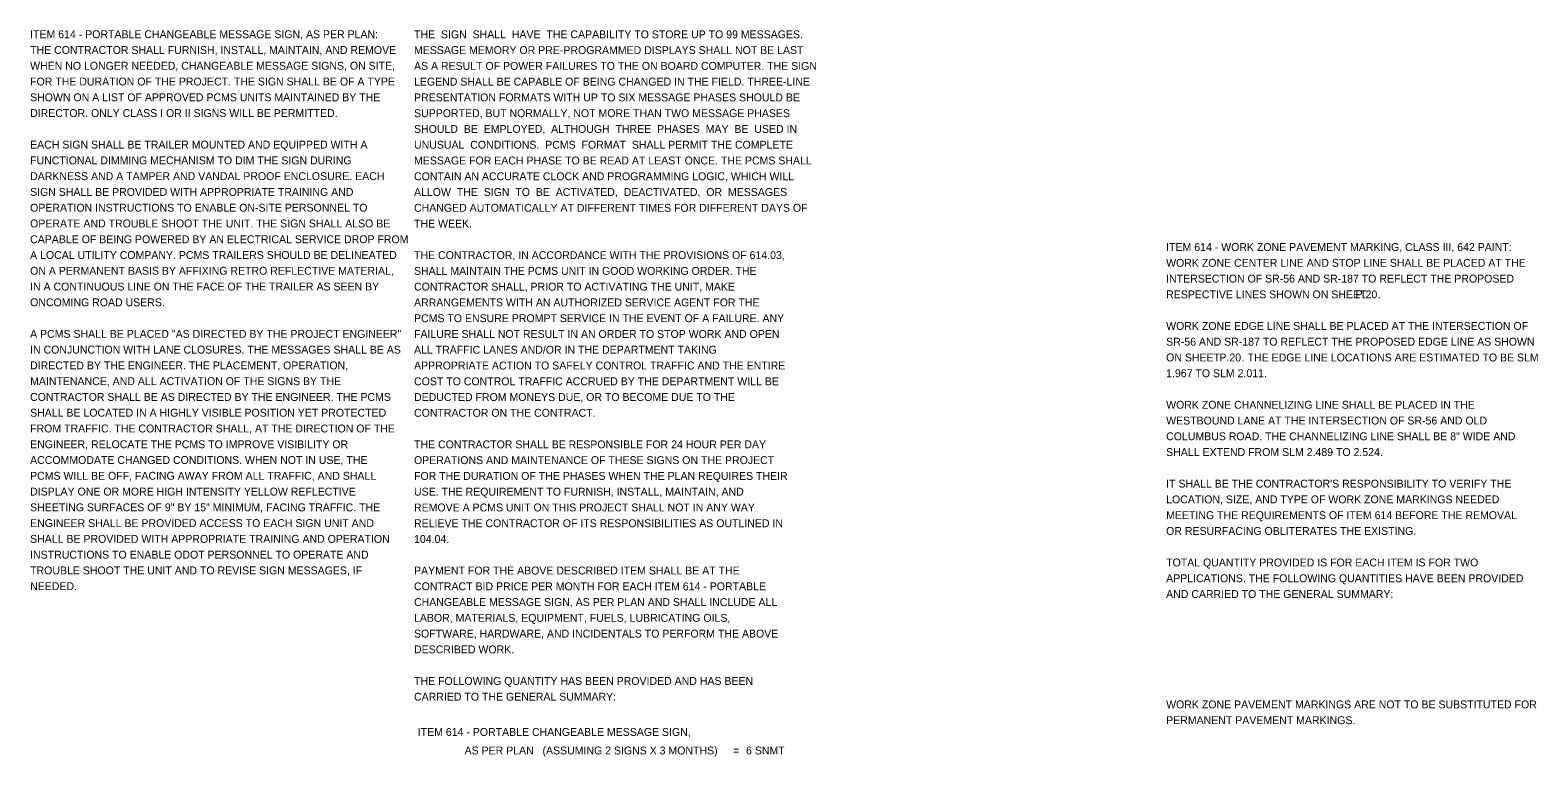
# Model space of a CAD drawing. Extents: x -7.9 to 64.5, y -13.1 to 23.6.
# Drawn here: x 37.77 to 64.55, y 7.89 to 20.79 of the extents above; entities that cross this region are included whole.
import ezdxf

# ---------------------------------------------------------------- set-up
doc = ezdxf.new("R2010")
doc.units = 0
doc.layers.add('SH_Text', color=7, linetype='Continuous')

msp = doc.modelspace()

# ---------------------------------------------------------------- texts
at = {"layer": 'SH_Text'}
for s, p in [('ITEM 614 - PORTABLE CHANGEABLE MESSAGE SIGN, AS PER PLAN:', (37.769, 20.651)), ('THE  SIGN  SHALL  HAVE  THE CAPABILITY TO STORE UP TO 99 MESSAGES.', (44.588, 20.649)), ('THE CONTRACTOR SHALL FURNISH, INSTALL, MAINTAIN, AND REMOVE ', (37.769, 20.371)), ('MESSAGE MEMORY OR PRE-PROGRAMMED DISPLAYS SHALL NOT BE LAST', (44.588, 20.369)), ('WHEN NO LONGER NEEDED, CHANGEABLE MESSAGE SIGNS, ON SITE, ', (37.769, 20.091)), ('AS A RESULT OF POWER FAILURES TO THE ON BOARD COMPUTER. THE SIGN', (44.588, 20.089)), ('FOR THE DURATION OF THE PROJECT. THE SIGN SHALL BE OF A TYPE ', (37.769, 19.811)), ('LEGEND SHALL BE CAPABLE OF BEING CHANGED IN THE FIELD. THREE-LINE', (44.588, 19.809)), ('SHOWN ON A LIST OF APPROVED PCMS UNITS MAINTAINED BY THE ', (37.769, 19.531)), ('PRESENTATION FORMATS WITH UP TO SIX MESSAGE PHASES SHOULD BE', (44.588, 19.529)), ('DIRECTOR. ONLY CLASS I OR II SIGNS WILL BE PERMITTED.', (37.769, 19.251)), ('SUPPORTED, BUT NORMALLY, NOT MORE THAN TWO MESSAGE PHASES', (44.588, 19.249)), ('SHOULD  BE  EMPLOYED,  ALTHOUGH  THREE  PHASES  MAY  BE  USED IN', (44.588, 18.969)), ('EACH SIGN SHALL BE TRAILER MOUNTED AND EQUIPPED WITH A ', (37.769, 18.691)), ('UNUSUAL  CONDITIONS.  PCMS  FORMAT  SHALL PERMIT THE COMPLETE', (44.588, 18.689)), ('FUNCTIONAL DIMMING MECHANISM TO DIM THE SIGN DURING ', (37.769, 18.411)), ('MESSAGE FOR EACH PHASE TO BE READ AT LEAST ONCE. THE PCMS SHALL', (44.588, 18.409)), ('DARKNESS AND A TAMPER AND VANDAL PROOF ENCLOSURE. EACH ', (37.769, 18.131)), ('CONTAIN AN ACCURATE CLOCK AND PROGRAMMING LOGIC, WHICH WILL', (44.588, 18.129)), ('SIGN SHALL BE PROVIDED WITH APPROPRIATE TRAINING AND ', (37.769, 17.851)), ('ALLOW  THE  SIGN  TO  BE  ACTIVATED,  DEACTIVATED,  OR  MESSAGES', (44.588, 17.849)), ('OPERATION INSTRUCTIONS TO ENABLE ON-SITE PERSONNEL TO ', (37.769, 17.571)), ('CHANGED AUTOMATICALLY AT DIFFERENT TIMES FOR DIFFERENT DAYS OF', (44.588, 17.569)), ('OPERATE AND TROUBLE SHOOT THE UNIT. THE SIGN SHALL ALSO BE ', (37.769, 17.291)), ('THE WEEK.', (44.588, 17.289)), ('CAPABLE OF BEING POWERED BY AN ELECTRICAL SERVICE DROP FROM ', (37.769, 17.011)), ('A LOCAL UTILITY COMPANY. PCMS TRAILERS SHOULD BE DELINEATED ', (37.769, 16.731)), ('ITEM 614 - WORK ZONE PAVEMENT MARKING, CLASS III, 642 PAINT:', (57.947, 16.872)), ('THE CONTRACTOR, IN ACCORDANCE WITH THE PROVISIONS OF 614.03, ', (44.588, 16.729)), ('WORK ZONE CENTER LINE AND STOP LINE SHALL BE PLACED AT THE ', (57.947, 16.592)), ('ON A PERMANENT BASIS BY AFFIXING RETRO REFLECTIVE MATERIAL, ', (37.769, 16.451)), ('SHALL MAINTAIN THE PCMS UNIT IN GOOD WORKING ORDER. THE ', (44.588, 16.449)), ('INTERSECTION OF SR-56 AND SR-187 TO REFLECT THE PROPOSED ', (57.947, 16.312)), ('IN A CONTINUOUS LINE ON THE FACE OF THE TRAILER AS SEEN BY ', (37.769, 16.171)), ('CONTRACTOR SHALL, PRIOR TO ACTIVATING THE UNIT, MAKE ', (44.588, 16.169)), ('RESPECTIVE LINES SHOWN ON SHEET ', (57.947, 16.032)), ('P.20', (61.312, 16.032)), ('ONCOMING ROAD USERS.', (37.769, 15.891)), ('ARRANGEMENTS WITH AN AUTHORIZED SERVICE AGENT FOR THE ', (44.588, 15.889)), ('.', (61.705, 16.032)), ('PCMS TO ENSURE PROMPT SERVICE IN THE EVENT OF A FAILURE. ANY ', (44.588, 15.609)), ('WORK ZONE EDGE LINE SHALL BE PLACED AT THE INTERSECTION OF ', (57.947, 15.472)), ('A PCMS SHALL BE PLACED "AS DIRECTED BY THE PROJECT ENGINEER" ', (37.769, 15.331)), ('FAILURE SHALL NOT RESULT IN AN ORDER TO STOP WORK AND OPEN ', (44.588, 15.329)), ('SR-56 AND SR-187 TO REFLECT THE PROPOSED EDGE LINE AS SHOWN ', (57.947, 15.192)), ('IN CONJUNCTION WITH LANE CLOSURES. THE MESSAGES SHALL BE AS ', (37.769, 15.051)), ('ALL TRAFFIC LANES AND/OR IN THE DEPARTMENT TAKING ', (44.588, 15.049)), ('ON SHEET ', (57.947, 14.912)), ('P.20', (58.893, 14.912)), (' THE EDGE LINE LOCATIONS ARE ESTIMATED TO BE SLM ', (59.342, 14.912)), ('DIRECTED BY THE ENGINEER. THE PLACEMENT, OPERATION, ', (37.769, 14.771)), ('APPROPRIATE ACTION TO SAFELY CONTROL TRAFFIC AND THE ENTIRE ', (44.588, 14.769)), ('1.967 TO SLM 2.011.', (57.947, 14.632)), ('.', (59.287, 14.912)), ('MAINTENANCE, AND ALL ACTIVATION OF THE SIGNS BY THE ', (37.769, 14.491)), ('COST TO CONTROL TRAFFIC ACCRUED BY THE DEPARTMENT WILL BE ', (44.588, 14.489)), ('CONTRACTOR SHALL BE AS DIRECTED BY THE ENGINEER. THE PCMS ', (37.769, 14.211)), ('DEDUCTED FROM MONEYS DUE, OR TO BECOME DUE TO THE ', (44.588, 14.209)), ('WORK ZONE CHANNELIZING LINE SHALL BE PLACED IN THE ', (57.947, 14.072)), ('SHALL BE LOCATED IN A HIGHLY VISIBLE POSITION YET PROTECTED ', (37.769, 13.931)), ('CONTRACTOR ON THE CONTRACT.', (44.588, 13.929)), ('WESTBOUND LANE AT THE INTERSECTION OF SR-56 AND OLD ', (57.947, 13.792)), ('FROM TRAFFIC. THE CONTRACTOR SHALL, AT THE DIRECTION OF THE ', (37.769, 13.651)), ('ENGINEER, RELOCATE THE PCMS TO IMPROVE VISIBILITY OR ', (37.769, 13.371)), ('THE CONTRACTOR SHALL BE RESPONSIBLE FOR 24 HOUR PER DAY ', (44.588, 13.369)), ('COLUMBUS ROAD. THE CHANNELIZING LINE SHALL BE 8" WIDE AND ', (57.947, 13.512)), ('ACCOMMODATE CHANGED CONDITIONS. WHEN NOT IN USE, THE ', (37.769, 13.091)), ('OPERATIONS AND MAINTENANCE OF THESE SIGNS ON THE PROJECT ', (44.588, 13.089)), ('SHALL EXTEND FROM SLM 2.489 TO 2.524.', (57.947, 13.232)), ('PCMS WILL BE OFF, FACING AWAY FROM ALL TRAFFIC, AND SHALL ', (37.769, 12.811)), ('FOR THE DURATION OF THE PHASES WHEN THE PLAN REQUIRES THEIR ', (44.588, 12.809)), ('DISPLAY ONE OR MORE HIGH INTENSITY YELLOW REFLECTIVE ', (37.769, 12.531)), ('USE. THE REQUIREMENT TO FURNISH, INSTALL, MAINTAIN, AND ', (44.588, 12.529)), ("IT SHALL BE THE CONTRACTOR'S RESPONSIBILITY TO VERIFY THE ", (57.947, 12.672)), ('SHEETING SURFACES OF 9" BY 15" MINIMUM, FACING TRAFFIC. THE ', (37.769, 12.251)), ('REMOVE A PCMS UNIT ON THIS PROJECT SHALL NOT IN ANY WAY ', (44.588, 12.249)), ('LOCATION, SIZE, AND TYPE OF WORK ZONE MARKINGS NEEDED ', (57.947, 12.392)), ('ENGINEER SHALL BE PROVIDED ACCESS TO EACH SIGN UNIT AND ', (37.769, 11.971)), ('RELIEVE THE CONTRACTOR OF ITS RESPONSIBILITIES AS OUTLINED IN ', (44.588, 11.969)), ('MEETING THE REQUIREMENTS OF ITEM 614 BEFORE THE REMOVAL ', (57.947, 12.112)), ('SHALL BE PROVIDED WITH APPROPRIATE TRAINING AND OPERATION ', (37.769, 11.691)), ('104.04.', (44.588, 11.689)), ('OR RESURFACING OBLITERATES THE EXISTING.', (57.947, 11.832)), ('INSTRUCTIONS TO ENABLE ODOT PERSONNEL TO OPERATE AND ', (37.769, 11.411)), ('TROUBLE SHOOT THE UNIT AND TO REVISE SIGN MESSAGES, IF ', (37.769, 11.131)), ('PAYMENT FOR THE ABOVE DESCRIBED ITEM SHALL BE AT THE ', (44.588, 11.129)), ('TOTAL QUANTITY PROVIDED IS FOR EACH ITEM IS FOR TWO ', (57.947, 11.272)), ('NEEDED.', (37.769, 10.851)), ('CONTRACT BID PRICE PER MONTH FOR EACH ITEM 614 - PORTABLE ', (44.588, 10.849)), ('APPLICATIONS. THE FOLLOWING QUANTITIES HAVE BEEN PROVIDED ', (57.947, 10.992)), ('AND CARRIED TO THE GENERAL SUMMARY:', (57.947, 10.712)), ('CHANGEABLE MESSAGE SIGN, AS PER PLAN AND SHALL INCLUDE ALL ', (44.588, 10.569)), ('LABOR, MATERIALS, EQUIPMENT, FUELS, LUBRICATING OILS, ', (44.588, 10.289)), ('SOFTWARE, HARDWARE, AND INCIDENTALS TO PERFORM THE ABOVE ', (44.588, 10.009)), ('DESCRIBED WORK.', (44.588, 9.729)), ('THE FOLLOWING QUANTITY HAS BEEN PROVIDED AND HAS BEEN ', (44.588, 9.169)), ('CARRIED TO THE GENERAL SUMMARY:', (44.588, 8.889)), ('WORK ZONE PAVEMENT MARKINGS ARE NOT TO BE SUBSTITUTED FOR ', (57.947, 8.752)), ('PERMANENT PAVEMENT MARKINGS.', (57.947, 8.472)), ('ITEM 614 - PORTABLE CHANGEABLE MESSAGE SIGN,', (44.654, 8.263)), ('                AS PER PLAN   (ASSUMING 2 SIGNS X 3 MONTHS)', (44.654, 7.934)), ('6 SNMT', (50.485, 7.934)), ('=', (50.256, 7.934))]:
    msp.add_text(s, height=0.14, dxfattribs=at).set_placement(p)

doc.saveas('drawing.dxf')
